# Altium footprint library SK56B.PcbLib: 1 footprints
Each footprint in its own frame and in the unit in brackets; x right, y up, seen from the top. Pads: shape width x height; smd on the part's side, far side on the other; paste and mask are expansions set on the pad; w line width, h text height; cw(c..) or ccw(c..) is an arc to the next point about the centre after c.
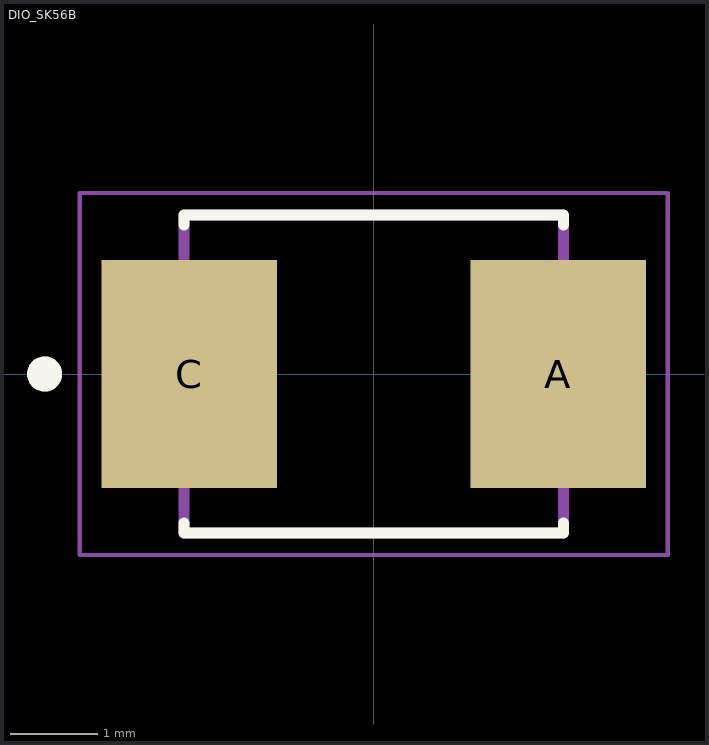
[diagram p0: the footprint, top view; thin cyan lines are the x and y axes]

## DIO_SK56B [mm]
height 2.65
pads (2):
  rect 2x2.6 smd: A(2.1,0) C(-2.1,0)
Top Overlay:
  circle w0.2: c-3.75,0 r0.1
  lines w0.127: -2.163,-1.7 -2.163,-1.813 2.163,-1.813 2.163,-1.7 ; -2.163,1.7 -2.163,1.813 2.163,1.813 2.163,1.7
Mechanical 13:
  circle w0.2: c-3.75,0 r0.1
  lines w0.127: -2.163,-1.813 2.163,-1.813 2.163,1.813 -2.163,1.813 -2.163,-1.813
Mechanical 15:
  lines w0.05: -3.35,-2.063 3.35,-2.063 3.35,2.063 -3.35,2.063 -3.35,-2.063
3D body "step_temp.STEP": height 2.65, standoff 0, extent -2.675,-1.813 2.675,1.813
